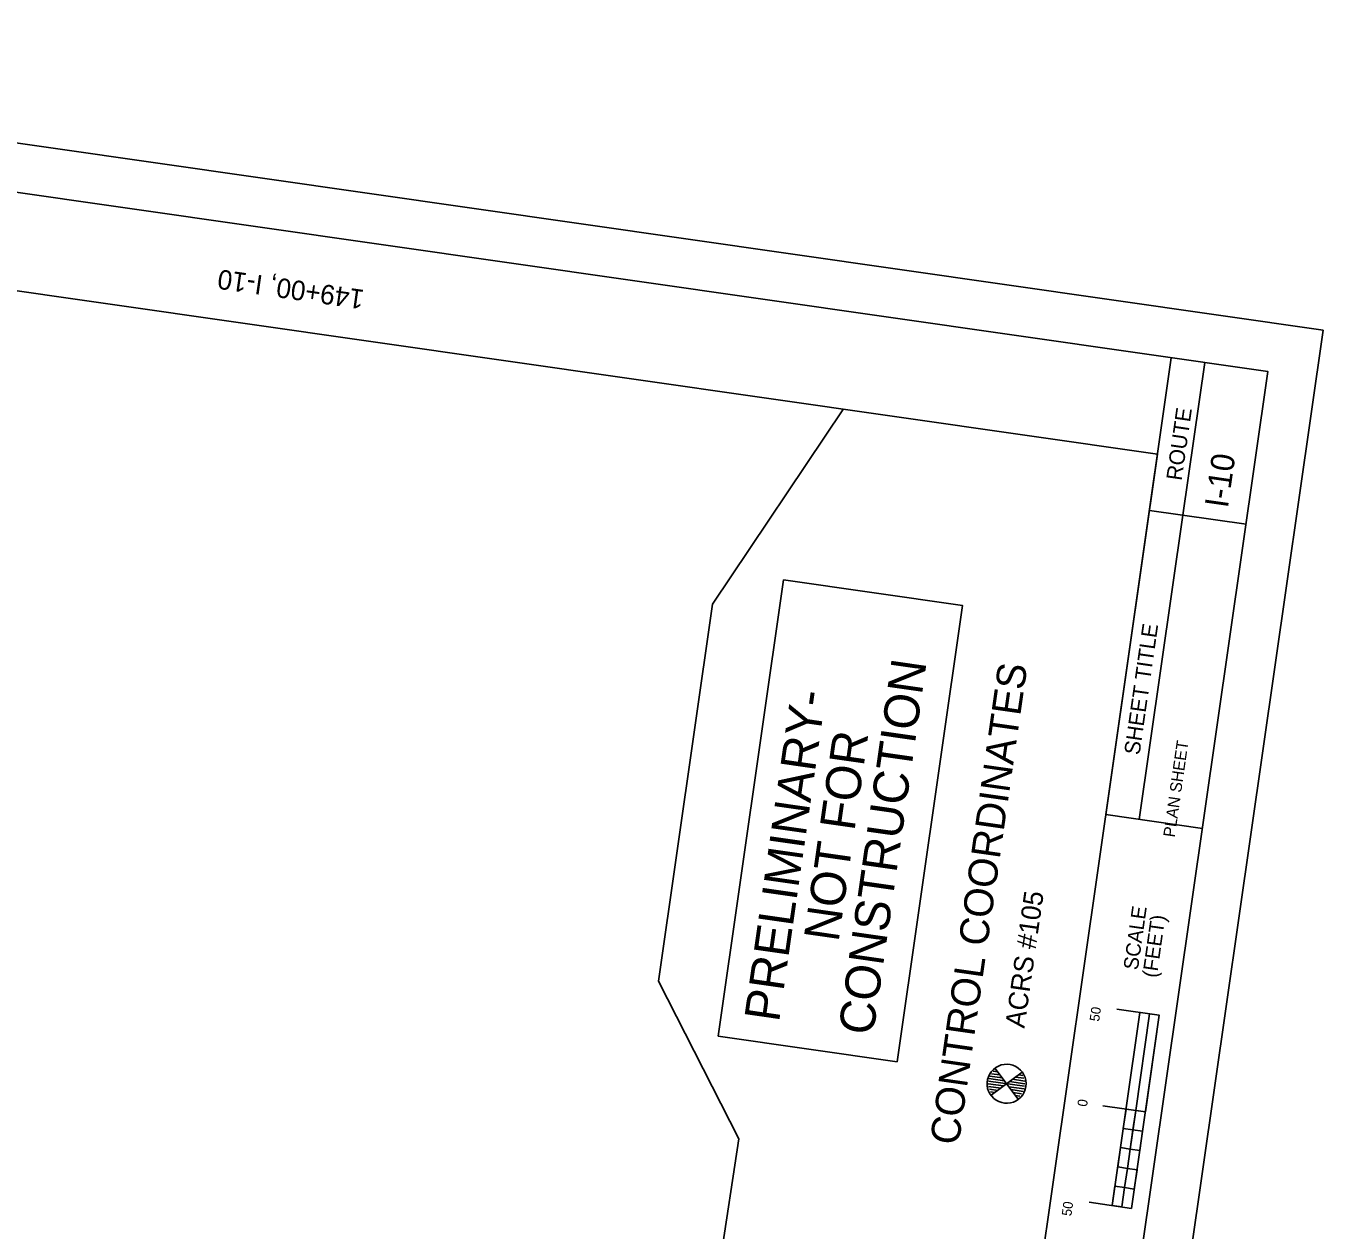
# Model space of a CAD drawing. Extents: x 1797205 to 1798536, y 248101 to 249940.
# Drawn here: x 1797871 to 1798536, y 249322 to 249940 of the extents above; entities that cross this region are included whole.
import ezdxf

# ---------------------------------------------------------------- set-up
doc = ezdxf.new("R2010")
doc.units = 0
for name, color, linetype in [('1', 7, 'Continuous'), ('29', 7, 'Continuous'), ('ANNO-SHT', 7, 'Continuous'), ('ANNO-SYMB', 7, 'Continuous'), ('ANNO-TXT', 7, 'Continuous'), ('CLOSURE', 7, 'Continuous'), ('Default', 7, 'Continuous'), ('Level 31', 7, 'Continuous'), ('Level 45', 7, 'Continuous'), ('Level 6', 7, 'Continuous'), ('Level 62', 7, 'Continuous'), ('SHT-BDR', 7, 'Continuous'), ('SHT-BNDRY', 7, 'Continuous')]:
    doc.layers.add(name, color=color, linetype=linetype)

# ---------------------------------------------------------------- blocks, each defined once
blk = doc.blocks.new('POINT_DISPLAY')
at = {"layer": 'Default'}
blk.add_line((0, 0), (0, 0), dxfattribs=at)

msp = doc.modelspace()

# ---------------------------------------------------------------- linework, layer by layer
at = {"layer": '1'}
msp.add_lwpolyline([(1798225.43, 249421.82), (1798258.97, 249655.85), (1798350.66, 249642.71), (1798317.12, 249408.68)], close=True, dxfattribs=at)
at = {"layer": '29'}
for p, q in [((1798222.54, 249643.35), (1798289.65, 249743.61)), ((1798194.84, 249450.08), (1798222.54, 249643.35)), ((1798236.04, 249369.16), (1798194.84, 249450.08)), ((1798203.57, 249158.34), (1798236.04, 249369.16))]:
    msp.add_line(p, q, dxfattribs=at)
at = {"layer": 'ANNO-SYMB'}
for p, q in [((1798441.63, 249433.96), (1798427.44, 249334.97)), ((1798451.52, 249432.54), (1798429.75, 249435.66)), ((1798451.52, 249432.54), (1798437.34, 249333.55)), ((1798451.52, 249432.54), (1798446.57, 249433.25)), ((1798451.52, 249432.54), (1798446.57, 249433.25)), ((1798451.52, 249432.54), (1798446.57, 249433.25)), ((1798444.43, 249383.05), (1798422.65, 249386.17)), ((1798444.43, 249383.05), (1798422.65, 249386.17)), ((1798444.43, 249383.05), (1798422.65, 249386.17)), ((1798439.48, 249383.75), (1798434.53, 249384.46)), ((1798439.48, 249383.75), (1798434.53, 249384.46)), ((1798439.48, 249383.75), (1798434.53, 249384.46)), ((1798439.48, 249383.75), (1798436.64, 249363.96)), ((1798433.81, 249344.16), (1798428.86, 249344.87)), ((1798433.81, 249344.16), (1798428.86, 249344.87)), ((1798437.34, 249333.55), (1798415.56, 249336.67))]:
    msp.add_line(p, q, dxfattribs=at)
for points in [[(1798439.48, 249383.75), (1798446.57, 249433.25), (1798451.52, 249432.54), (1798444.43, 249383.05)], [(1798433.11, 249374.57), (1798434.53, 249384.46), (1798439.48, 249383.75), (1798438.06, 249373.86)], [(1798436.64, 249363.96), (1798438.06, 249373.86), (1798443.01, 249373.15), (1798441.59, 249363.25)], [(1798430.28, 249354.77), (1798431.69, 249364.67), (1798436.64, 249363.96), (1798435.22, 249354.06)], [(1798433.81, 249344.16), (1798435.22, 249354.06), (1798440.17, 249353.35), (1798438.76, 249343.45)], [(1798427.44, 249334.97), (1798428.86, 249344.87), (1798433.81, 249344.16), (1798432.39, 249334.26)]]:
    msp.add_lwpolyline(points, close=True, dxfattribs=at)
at = {"layer": 'ANNO-TXT'}
for p, q in [((1798463.66, 249689.03), (1798474.88, 249767.29)), ((1798441.3, 249532.98), (1798463.66, 249689.03))]:
    msp.add_line(p, q, dxfattribs=at)
at = {"layer": 'CLOSURE'}
for p, q in [((1798367.74, 249405.77), (1798366.54, 249404.83)), ((1798369.08, 249406.52), (1798367.74, 249405.77)), ((1798370.51, 249407.06), (1798369.08, 249406.52)), ((1798372.01, 249407.37), (1798370.51, 249407.06)), ((1798373.54, 249407.45), (1798372.01, 249407.37)), ((1798375.06, 249407.29), (1798373.54, 249407.45)), ((1798376.54, 249406.9), (1798375.06, 249407.29)), ((1798377.95, 249406.3), (1798376.54, 249406.9)), ((1798379.25, 249405.48), (1798377.95, 249406.3)), ((1798363.52, 249399.61), (1798363.3, 249398.09)), ((1798363.96, 249401.07), (1798363.52, 249399.61)), ((1798364.62, 249402.45), (1798363.96, 249401.07)), ((1798364.23, 249400.08), (1798372.15, 249398.96)), ((1798365.49, 249403.71), (1798364.62, 249402.45)), ((1798364.75, 249401.35), (1798371.02, 249400.46)), ((1798365.37, 249391.5), (1798381.2, 249403.4)), ((1798366.54, 249404.83), (1798365.49, 249403.71)), ((1798365.59, 249402.58), (1798369.88, 249401.97)), ((1798366.44, 249403.81), (1798368.75, 249403.48)), ((1798367.33, 249405.36), (1798379.23, 249389.54)), ((1798376.3, 249399.72), (1798382.57, 249398.83)), ((1798377.81, 249400.85), (1798382.1, 249400.24)), ((1798380.4, 249404.48), (1798379.25, 249405.48)), ((1798379.31, 249401.98), (1798381.62, 249401.66)), ((1798381.39, 249403.31), (1798380.4, 249404.48)), ((1798382.19, 249402), (1798381.39, 249403.31)), ((1798382.78, 249400.59), (1798382.19, 249402)), ((1798383.15, 249399.1), (1798382.78, 249400.59)), ((1798383.28, 249397.58), (1798383.15, 249399.1)), ((1798363.3, 249398.09), (1798363.32, 249396.56)), ((1798363.32, 249396.56), (1798363.58, 249395.05)), ((1798363.58, 249395.05), (1798364.06, 249393.6)), ((1798363.86, 249397.44), (1798371.78, 249396.32)), ((1798364, 249396.07), (1798370.27, 249395.18)), ((1798364.04, 249398.76), (1798382.53, 249396.14)), ((1798364.06, 249393.6), (1798364.75, 249392.23)), ((1798364.47, 249394.66), (1798368.76, 249394.05)), ((1798364.95, 249393.24), (1798367.26, 249392.92)), ((1798382.34, 249394.82), (1798374.42, 249395.94)), ((1798382.71, 249397.46), (1798374.79, 249398.58)), ((1798375.55, 249394.44), (1798381.82, 249393.55)), ((1798376.68, 249392.93), (1798380.97, 249392.32)), ((1798381.54, 249391.8), (1798382.3, 249393.13)), ((1798382.3, 249393.13), (1798382.86, 249394.55)), ((1798382.86, 249394.55), (1798383.19, 249396.05)), ((1798383.19, 249396.05), (1798383.28, 249397.58)), ((1798364.75, 249392.23), (1798365.65, 249390.99)), ((1798365.65, 249390.99), (1798366.73, 249389.9)), ((1798366.73, 249389.9), (1798367.95, 249388.99)), ((1798367.95, 249388.99), (1798369.31, 249388.27)), ((1798369.31, 249388.27), (1798370.76, 249387.77)), ((1798370.76, 249387.77), (1798372.26, 249387.5)), ((1798372.26, 249387.5), (1798373.79, 249387.46)), ((1798373.79, 249387.46), (1798375.31, 249387.66)), ((1798375.31, 249387.66), (1798376.78, 249388.08)), ((1798376.78, 249388.08), (1798378.17, 249388.73)), ((1798377.82, 249391.42), (1798380.13, 249391.1)), ((1798378.17, 249388.73), (1798379.45, 249389.57)), ((1798379.45, 249389.57), (1798380.58, 249390.61)), ((1798380.58, 249390.61), (1798381.54, 249391.8))]:
    msp.add_line(p, q, dxfattribs=at)
at = {"layer": 'Level 6'}
msp.add_line((1798457.7, 249769.75), (1798424.12, 249535.44), dxfattribs=at)
at = {"layer": 'Level 62'}
msp.add_lwpolyline([(1798294.36, 248101.04), (1798535.54, 249783.85), (1797446.66, 249939.91), (1797205.48, 248257.1)], close=True, dxfattribs=at)
at = {"layer": 'SHT-BDR'}
msp.add_lwpolyline([(1798237.8, 248235.41), (1798450.6, 249720.24), (1797510.21, 249855.02), (1797297.4, 248370.19)], close=True, dxfattribs=at)
at = {"layer": 'SHT-BNDRY'}
for p, q in [((1798496.03, 249684.39), (1798446.48, 249691.49)), ((1798473.66, 249528.34), (1798424.12, 249535.44))]:
    msp.add_line(p, q, dxfattribs=at)
msp.add_lwpolyline([(1798278.47, 248166.46), (1798507.24, 249762.65), (1797467.86, 249911.62), (1797239.09, 248315.42)], close=True, dxfattribs=at)

# ---------------------------------------------------------------- block references
at = {"layer": 'CLOSURE', "xscale": 1.9999999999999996, "yscale": 2, "rotation": -8.056202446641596}
msp.add_blockref('POINT_DISPLAY', (1798373.28, 249397.45), dxfattribs=at)

# ---------------------------------------------------------------- texts
at = {"layer": '1'}
for s, p in [('CONSTRUCTION', (1798304.81, 249421.77)), ('PRELIMINARY-', (1798256.59, 249428.65)), ('NOT FOR', (1798287.09, 249469.77))]:
    msp.add_text(s, height=18, rotation=81.84389, dxfattribs=at).set_placement(p)
at = {"layer": 'ANNO-SHT'}
for s, height, rotation, p in [('149+00, I-10', 10, 171.84389, (1798044.33, 249804.43)), ('  I-10  ', 12, 81.84389, (1798485.44, 249683.49)), ('               PLAN SHEET               ', 6, 81.84389, (1798454.75, 249490.46))]:
    msp.add_text(s, height=height, rotation=rotation, dxfattribs=at).set_placement(p)
at = {"layer": 'ANNO-SYMB'}
for s, height, p in [('SCALE', 7.497, (1798440.56, 249455.46)), ('(FEET)', 7.497, (1798450.24, 249451.54)), (' 50', 4.996, (1798420.47, 249427.3)), ('0', 5, (1798414.47, 249385.45)), ('0', 5, (1798414.47, 249385.45)), ('0', 5, (1798414.47, 249385.45)), (' 50', 4.996, (1798406.17, 249327.49))]:
    msp.add_text(s, height=height, rotation=81.90109, dxfattribs=at).set_placement(p)
at = {"layer": 'ANNO-TXT'}
for s, p in [('ROUTE', (1798463.02, 249706.45)), ('SHEET TITLE', (1798441.43, 249565.73))]:
    msp.add_text(s, height=8, rotation=81.84389, dxfattribs=at).set_placement(p)
at = {"layer": 'Level 31'}
msp.add_text('ACRS #105', height=10, rotation=81.8439, dxfattribs=at).set_placement((1798382.39, 249425.61))
at = {"layer": 'Level 45'}
msp.add_text('CONTROL COORDINATES', height=14.8986, rotation=81.84393, dxfattribs=at).set_placement((1798348.68, 249365.52))

doc.saveas('drawing.dxf')
